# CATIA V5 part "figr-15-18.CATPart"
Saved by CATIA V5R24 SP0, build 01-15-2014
Part number: Part1
Bounding box of the stored display mesh (mm): x -46.56 to 46.56, y -38.965 to 25.965, z 0 to 40
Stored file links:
  D:\KAVITA\CATIA V5-6R2014 Project_ Kavita\CATIA V5-6R2014_partfiles\Partfiles\c15_catia_v5-6r2014_prt\figr-15-18.CATPart
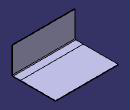
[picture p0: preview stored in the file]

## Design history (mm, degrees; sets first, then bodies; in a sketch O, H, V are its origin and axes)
SheetMetalParameters1: Thickness 1, BendRadius 1, KFactor 0.325257 {= log(min(100,max(20*SheetMetalParameters1.BendRadius,SheetMetalParameters1.Thickness)/SheetMetalParameters1.Thickness))/log(100)/2}, ReliefRadialLength 1, ReliefAxialLength 2, MinimumBendRadius 0
Body1 (main body)
  Sketch1 on xy-plane, origin (0, 0, 0), H (1, 0, 0), V (0, 1, 0)
    line L1 (-46.5596, 25.9646) -> (46.5596, 25.9646)
    line L2 (46.5596, 25.9646) -> (46.5596, -25.9646)
    line L3 (46.5596, -25.9646) -> (-46.5596, -25.9646)
    line L4 (-46.5596, -25.9646) -> (-46.5596, 25.9646)
    horizontal: L1 H, L3 H
    vertical: L2 V, L4 V
    symmetry: L1 L3 H, L4 L2 V
  Wall1: Thickness 1, Profile Sketch1
  d_NewWallOnEdge1: NewWallOnEdge_Edge edge [face of Wall1 | face of Wall1], NewWallOnEdge_Length 40, NewWallOnEdge_HeightLimitOffset 0, NewWallOnEdge_WidthOffset1 0, NewWallOnEdge_WidthOffset2 0, NewWallOnEdge_Angle 90, NewWallOnEdge_BendRadiusValue 1 {= SheetMetalParameters1.BendRadius}, NewWallOnEdge_BendTable SheetMetalParameters1, KFacteur 0.325257 {= log(min(100,max(20*d_NewWallOnEdge1.Radius,SheetMetalParameters1.Thickness)/SheetMetalParameters1.Thickness))/log(100)/2}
